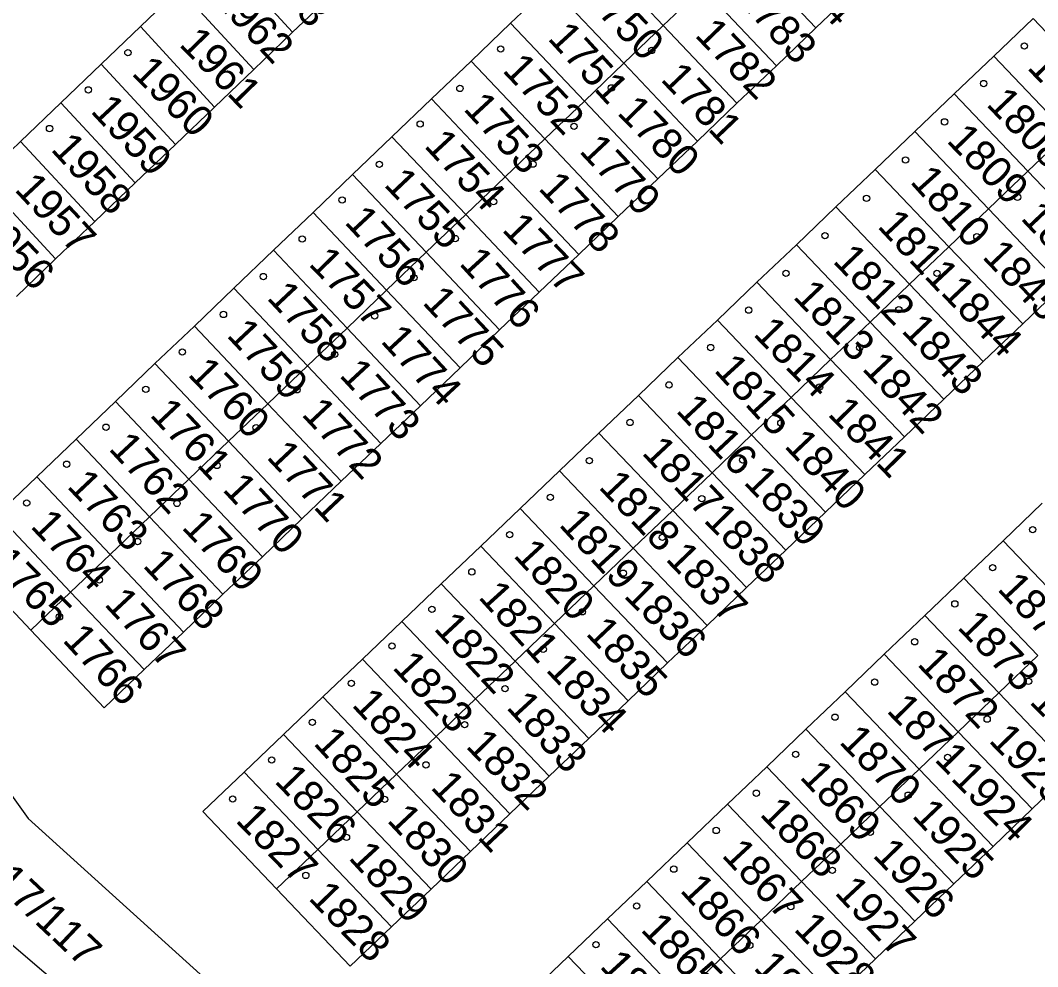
# Model space of a CAD drawing. Extents: x -735249 to -729401, y -1124843 to -1121828.
# Drawn here: x -733413.7 to -733357.4, y -1123266.5 to -1123214.1 of the extents above; entities that cross this region are included whole.
import ezdxf

# ---------------------------------------------------------------- set-up
doc = ezdxf.new("R2010")
doc.units = 0
for name, color, linetype in [('Vrstva 1', 7, 'Continuous'), ('Vrstva 18', 7, 'Continuous'), ('Vrstva 19', 7, 'Continuous'), ('Vrstva 25', 7, 'Continuous')]:
    doc.layers.add(name, color=color, linetype=linetype)

msp = doc.modelspace()

# ---------------------------------------------------------------- linework, layer by layer
at = {"layer": 'Vrstva 1'}
for points in [[(-733382.16, -1123210.08), (-733378.09, -1123214.39)], [(-733402.71, -1123210.3), (-733398.61, -1123214.76)], [(-733373.72, -1123210.21), (-733369.64, -1123214.52)], [(-733407.04, -1123214.45), (-733404.87, -1123212.36)], [(-733404.87, -1123212.36), (-733400.76, -1123216.82)], [(-733384.35, -1123212.17), (-733386.54, -1123214.26)], [(-733384.35, -1123212.17), (-733380.27, -1123216.47)], [(-733378.09, -1123214.39), (-733375.9, -1123212.3)], [(-733375.9, -1123212.3), (-733371.83, -1123216.61)], [(-733398.61, -1123214.76), (-733396.44, -1123212.69)], [(-733369.64, -1123214.52), (-733367.46, -1123212.43)], [(-733359.8, -1123216.09), (-733357.62, -1123214)], [(-733357.62, -1123214), (-733353.54, -1123218.28)], [(-733409.21, -1123216.52), (-733407.04, -1123214.45)], [(-733407.04, -1123214.45), (-733402.94, -1123218.9)], [(-733386.54, -1123214.26), (-733388.73, -1123216.36)], [(-733386.54, -1123214.26), (-733382.46, -1123218.57)], [(-733380.27, -1123216.47), (-733378.09, -1123214.39)], [(-733378.09, -1123214.39), (-733374.01, -1123218.69)], [(-733371.83, -1123216.61), (-733369.64, -1123214.52)], [(-733400.76, -1123216.82), (-733398.61, -1123214.76)], [(-733361.99, -1123218.17), (-733359.8, -1123216.09)], [(-733359.8, -1123216.09), (-733355.72, -1123220.37)], [(-733411.44, -1123218.66), (-733409.21, -1123216.52)], [(-733409.21, -1123216.52), (-733405.1, -1123220.97)], [(-733402.94, -1123218.9), (-733400.76, -1123216.82)], [(-733388.73, -1123216.36), (-733390.92, -1123218.45)], [(-733388.73, -1123216.36), (-733384.65, -1123220.66)], [(-733382.46, -1123218.57), (-733380.27, -1123216.47)], [(-733380.27, -1123216.47), (-733376.2, -1123220.78)], [(-733374.01, -1123218.69), (-733371.83, -1123216.61)], [(-733390.92, -1123218.45), (-733393.11, -1123220.55)], [(-733390.92, -1123218.45), (-733386.84, -1123222.76)], [(-733384.65, -1123220.66), (-733382.46, -1123218.57)], [(-733382.46, -1123218.57), (-733378.39, -1123222.87)], [(-733364.17, -1123220.26), (-733361.99, -1123218.17)], [(-733361.99, -1123218.17), (-733357.91, -1123222.45)], [(-733413.67, -1123220.8), (-733411.44, -1123218.66)], [(-733411.44, -1123218.66), (-733407.33, -1123223.1)], [(-733405.1, -1123220.97), (-733402.94, -1123218.9)], [(-733376.2, -1123220.78), (-733374.01, -1123218.69)], [(-733366.36, -1123222.35), (-733364.17, -1123220.26)], [(-733364.17, -1123220.26), (-733360.09, -1123224.54)], [(-733415.84, -1123222.87), (-733413.67, -1123220.8)], [(-733413.67, -1123220.8), (-733409.57, -1123225.24)], [(-733393.11, -1123220.55), (-733395.29, -1123222.64)], [(-733393.11, -1123220.55), (-733389.03, -1123224.85)], [(-733386.84, -1123222.76), (-733384.65, -1123220.66)], [(-733384.65, -1123220.66), (-733380.58, -1123224.96)], [(-733378.39, -1123222.87), (-733376.2, -1123220.78)], [(-733357.91, -1123222.45), (-733355.72, -1123220.37)], [(-733407.33, -1123223.1), (-733405.1, -1123220.97)], [(-733368.54, -1123224.43), (-733366.36, -1123222.35)], [(-733366.36, -1123222.35), (-733362.28, -1123226.63)], [(-733360.09, -1123224.54), (-733357.91, -1123222.45)], [(-733357.91, -1123222.45), (-733353.82, -1123226.73)], [(-733415.84, -1123222.87), (-733411.73, -1123227.31)], [(-733409.57, -1123225.24), (-733407.33, -1123223.1)], [(-733395.29, -1123222.64), (-733397.48, -1123224.73)], [(-733395.29, -1123222.64), (-733391.22, -1123226.94)], [(-733389.03, -1123224.85), (-733386.84, -1123222.76)], [(-733386.84, -1123222.76), (-733382.77, -1123227.06)], [(-733380.58, -1123224.96), (-733378.39, -1123222.87)], [(-733397.48, -1123224.73), (-733399.67, -1123226.83)], [(-733397.48, -1123224.73), (-733393.41, -1123229.04)], [(-733370.72, -1123226.52), (-733368.54, -1123224.43)], [(-733368.54, -1123224.43), (-733364.46, -1123228.71)], [(-733362.28, -1123226.63), (-733360.09, -1123224.54)], [(-733360.09, -1123224.54), (-733356.01, -1123228.81)], [(-733436.9, -1123225.24), (-733413.25, -1123258.27)], [(-733411.73, -1123227.31), (-733409.57, -1123225.24)], [(-733391.22, -1123226.94), (-733389.03, -1123224.85)], [(-733389.03, -1123224.85), (-733384.96, -1123229.15)], [(-733382.77, -1123227.06), (-733380.58, -1123224.96)], [(-733399.67, -1123226.83), (-733401.86, -1123228.92)], [(-733399.67, -1123226.83), (-733395.6, -1123231.13)], [(-733393.41, -1123229.04), (-733391.22, -1123226.94)], [(-733391.22, -1123226.94), (-733387.15, -1123231.24)], [(-733372.91, -1123228.6), (-733370.72, -1123226.52)], [(-733370.72, -1123226.52), (-733366.64, -1123230.8)], [(-733364.46, -1123228.71), (-733362.28, -1123226.63)], [(-733362.28, -1123226.63), (-733358.19, -1123230.9)], [(-733413.9, -1123229.38), (-733411.73, -1123227.31)], [(-733384.96, -1123229.15), (-733382.77, -1123227.06)], [(-733375.09, -1123230.69), (-733372.91, -1123228.6)], [(-733372.91, -1123228.6), (-733368.83, -1123232.88)], [(-733366.64, -1123230.8), (-733364.46, -1123228.71)], [(-733364.46, -1123228.71), (-733360.38, -1123232.99)], [(-733401.86, -1123228.92), (-733404.05, -1123231.02)], [(-733401.86, -1123228.92), (-733397.79, -1123233.22)], [(-733395.6, -1123231.13), (-733393.41, -1123229.04)], [(-733393.41, -1123229.04), (-733389.34, -1123233.33)], [(-733387.15, -1123231.24), (-733384.96, -1123229.15)], [(-733358.19, -1123230.9), (-733356.01, -1123228.81)], [(-733377.28, -1123232.77), (-733375.09, -1123230.69)], [(-733375.09, -1123230.69), (-733371.01, -1123234.97)], [(-733368.83, -1123232.88), (-733366.64, -1123230.8)], [(-733366.64, -1123230.8), (-733362.56, -1123235.07)], [(-733360.38, -1123232.99), (-733358.19, -1123230.9)], [(-733404.05, -1123231.02), (-733406.24, -1123233.1)], [(-733404.05, -1123231.02), (-733399.98, -1123235.32)], [(-733397.79, -1123233.22), (-733395.6, -1123231.13)], [(-733395.6, -1123231.13), (-733391.53, -1123235.43)], [(-733387.15, -1123231.24), (-733389.34, -1123233.33)], [(-733408.42, -1123235.19), (-733406.24, -1123233.1)], [(-733406.24, -1123233.1), (-733402.16, -1123237.4)], [(-733399.98, -1123235.32), (-733397.79, -1123233.22)], [(-733397.79, -1123233.22), (-733393.72, -1123237.52)], [(-733379.46, -1123234.86), (-733377.28, -1123232.77)], [(-733377.28, -1123232.77), (-733373.2, -1123237.05)], [(-733371.01, -1123234.97), (-733368.83, -1123232.88)], [(-733368.83, -1123232.88), (-733364.74, -1123237.16)], [(-733362.56, -1123235.07), (-733360.38, -1123232.99)], [(-733389.34, -1123233.33), (-733391.53, -1123235.43)], [(-733381.65, -1123236.95), (-733379.46, -1123234.86)], [(-733379.46, -1123234.86), (-733375.38, -1123239.14)], [(-733410.6, -1123237.28), (-733408.42, -1123235.19)], [(-733408.42, -1123235.19), (-733404.35, -1123239.49)], [(-733402.16, -1123237.4), (-733399.98, -1123235.32)], [(-733399.98, -1123235.32), (-733395.92, -1123239.61)], [(-733391.53, -1123235.43), (-733393.72, -1123237.52)], [(-733373.2, -1123237.05), (-733371.01, -1123234.97)], [(-733371.01, -1123234.97), (-733366.93, -1123239.24)], [(-733364.74, -1123237.16), (-733362.56, -1123235.07)], [(-733383.83, -1123239.03), (-733381.65, -1123236.95)], [(-733381.65, -1123236.95), (-733377.57, -1123241.23)], [(-733375.38, -1123239.14), (-733373.2, -1123237.05)], [(-733373.2, -1123237.05), (-733369.11, -1123241.33)], [(-733366.93, -1123239.24), (-733364.74, -1123237.16)], [(-733410.6, -1123237.28), (-733412.78, -1123239.37)], [(-733410.6, -1123237.28), (-733406.53, -1123241.58)], [(-733404.35, -1123239.49), (-733402.16, -1123237.4)], [(-733402.16, -1123237.4), (-733398.1, -1123241.7)], [(-733393.72, -1123237.52), (-733395.92, -1123239.61)], [(-733412.78, -1123239.37), (-733414.97, -1123241.45)], [(-733412.78, -1123239.37), (-733408.71, -1123243.67)], [(-733386.01, -1123241.12), (-733383.83, -1123239.03)], [(-733383.83, -1123239.03), (-733379.75, -1123243.31)], [(-733377.57, -1123241.23), (-733375.38, -1123239.14)], [(-733375.38, -1123239.14), (-733371.3, -1123243.42)], [(-733369.11, -1123241.33), (-733366.93, -1123239.24)], [(-733406.53, -1123241.58), (-733404.35, -1123239.49)], [(-733404.35, -1123239.49), (-733400.28, -1123243.79)], [(-733395.92, -1123239.61), (-733398.1, -1123241.7)], [(-733388.2, -1123243.2), (-733386.01, -1123241.12)], [(-733386.01, -1123241.12), (-733381.93, -1123245.4)], [(-733359.28, -1123242.91), (-733357.11, -1123240.83)], [(-733414.97, -1123241.45), (-733410.9, -1123245.75)], [(-733408.71, -1123243.67), (-733406.53, -1123241.58)], [(-733406.53, -1123241.58), (-733402.47, -1123245.87)], [(-733379.75, -1123243.31), (-733377.57, -1123241.23)], [(-733377.57, -1123241.23), (-733373.48, -1123245.5)], [(-733371.3, -1123243.42), (-733369.11, -1123241.33)], [(-733398.1, -1123241.7), (-733400.28, -1123243.79)], [(-733390.38, -1123245.29), (-733388.2, -1123243.2)], [(-733388.2, -1123243.2), (-733384.12, -1123247.48)], [(-733381.93, -1123245.4), (-733379.75, -1123243.31)], [(-733379.75, -1123243.31), (-733375.66, -1123247.59)], [(-733361.45, -1123244.98), (-733359.28, -1123242.91)], [(-733359.28, -1123242.91), (-733355.18, -1123247.19)], [(-733417.17, -1123243.56), (-733413.1, -1123247.86)], [(-733410.9, -1123245.75), (-733408.71, -1123243.67)], [(-733408.71, -1123243.67), (-733404.65, -1123247.96)], [(-733400.28, -1123243.79), (-733402.47, -1123245.87)], [(-733373.48, -1123245.5), (-733371.3, -1123243.42)], [(-733363.61, -1123247.05), (-733361.45, -1123244.98)], [(-733361.45, -1123244.98), (-733357.35, -1123249.26)], [(-733392.57, -1123247.37), (-733390.38, -1123245.29)], [(-733390.38, -1123245.29), (-733386.3, -1123249.57)], [(-733384.12, -1123247.48), (-733381.93, -1123245.4)], [(-733381.93, -1123245.4), (-733377.85, -1123249.67)], [(-733375.66, -1123247.59), (-733373.48, -1123245.5)], [(-733413.1, -1123247.86), (-733410.9, -1123245.75)], [(-733410.9, -1123245.75), (-733406.83, -1123250.04)], [(-733402.47, -1123245.87), (-733404.65, -1123247.96)], [(-733365.86, -1123249.19), (-733363.61, -1123247.05)], [(-733363.61, -1123247.05), (-733359.52, -1123251.33)], [(-733413.1, -1123247.86), (-733409.04, -1123252.15)], [(-733394.75, -1123249.46), (-733392.57, -1123247.37)], [(-733392.57, -1123247.37), (-733388.49, -1123251.65)], [(-733386.3, -1123249.57), (-733384.12, -1123247.48)], [(-733384.12, -1123247.48), (-733380.03, -1123251.76)], [(-733377.85, -1123249.67), (-733375.66, -1123247.59)], [(-733404.65, -1123247.96), (-733406.83, -1123250.04)], [(-733396.94, -1123251.55), (-733394.75, -1123249.46)], [(-733394.75, -1123249.46), (-733390.67, -1123253.74)], [(-733388.49, -1123251.65), (-733386.3, -1123249.57)], [(-733386.3, -1123249.57), (-733382.22, -1123253.85)], [(-733368.02, -1123251.27), (-733365.86, -1123249.19)], [(-733365.86, -1123249.19), (-733361.76, -1123253.48)], [(-733359.52, -1123251.33), (-733357.35, -1123249.26)], [(-733406.83, -1123250.04), (-733409.04, -1123252.15)], [(-733380.03, -1123251.76), (-733377.85, -1123249.67)], [(-733370.19, -1123253.34), (-733368.02, -1123251.27)], [(-733368.02, -1123251.27), (-733363.93, -1123255.55)], [(-733399.12, -1123253.63), (-733396.94, -1123251.55)], [(-733396.94, -1123251.55), (-733392.86, -1123255.83)], [(-733390.67, -1123253.74), (-733388.49, -1123251.65)], [(-733388.49, -1123251.65), (-733384.4, -1123255.93)], [(-733382.22, -1123253.85), (-733380.03, -1123251.76)], [(-733361.76, -1123253.48), (-733359.52, -1123251.33)], [(-733359.52, -1123251.33), (-733355.43, -1123255.61)], [(-733372.36, -1123255.41), (-733370.19, -1123253.34)], [(-733370.19, -1123253.34), (-733366.1, -1123257.62)], [(-733363.93, -1123255.55), (-733361.76, -1123253.48)], [(-733361.76, -1123253.48), (-733357.67, -1123257.75)], [(-733401.3, -1123255.72), (-733399.12, -1123253.63)], [(-733399.12, -1123253.63), (-733395.04, -1123257.91)], [(-733392.86, -1123255.83), (-733390.67, -1123253.74)], [(-733390.67, -1123253.74), (-733386.58, -1123258.02)], [(-733384.4, -1123255.93), (-733382.22, -1123253.85)], [(-733403.59, -1123257.9), (-733401.3, -1123255.72)], [(-733401.3, -1123255.72), (-733397.22, -1123260)], [(-733374.53, -1123257.48), (-733372.36, -1123255.41)], [(-733372.36, -1123255.41), (-733368.27, -1123259.7)], [(-733366.1, -1123257.62), (-733363.93, -1123255.55)], [(-733363.93, -1123255.55), (-733359.83, -1123259.83)], [(-733357.67, -1123257.75), (-733355.43, -1123255.61)], [(-733395.04, -1123257.91), (-733392.86, -1123255.83)], [(-733392.86, -1123255.83), (-733388.77, -1123260.11)], [(-733386.58, -1123258.02), (-733384.4, -1123255.93)], [(-733403.59, -1123257.9), (-733399.51, -1123262.18)], [(-733397.22, -1123260), (-733395.04, -1123257.91)], [(-733395.04, -1123257.91), (-733390.95, -1123262.19)], [(-733388.77, -1123260.11), (-733386.58, -1123258.02)], [(-733376.77, -1123259.63), (-733374.53, -1123257.48)], [(-733374.53, -1123257.48), (-733370.44, -1123261.77)], [(-733368.27, -1123259.7), (-733366.1, -1123257.62)], [(-733366.1, -1123257.62), (-733362, -1123261.9)], [(-733359.83, -1123259.83), (-733357.67, -1123257.75)], [(-733413.25, -1123258.27), (-733359.58, -1123306.83)], [(-733421.63, -1123258.87), (-733396.24, -1123280.58)], [(-733379.01, -1123261.77), (-733376.77, -1123259.63)], [(-733376.77, -1123259.63), (-733372.68, -1123263.91)], [(-733370.44, -1123261.77), (-733368.27, -1123259.7)], [(-733368.27, -1123259.7), (-733364.17, -1123263.97)], [(-733399.51, -1123262.18), (-733397.22, -1123260)], [(-733397.22, -1123260), (-733393.13, -1123264.28)], [(-733390.95, -1123262.19), (-733388.77, -1123260.11)], [(-733362, -1123261.9), (-733359.83, -1123259.83)], [(-733381.18, -1123263.84), (-733379.01, -1123261.77)], [(-733379.01, -1123261.77), (-733374.92, -1123266.05)], [(-733372.68, -1123263.91), (-733370.44, -1123261.77)], [(-733370.44, -1123261.77), (-733366.34, -1123266.05)], [(-733364.17, -1123263.97), (-733362, -1123261.9)], [(-733399.51, -1123262.18), (-733395.42, -1123266.46)], [(-733393.13, -1123264.28), (-733390.95, -1123262.19)], [(-733383.35, -1123265.91), (-733381.18, -1123263.84)], [(-733381.18, -1123263.84), (-733377.08, -1123268.13)], [(-733374.92, -1123266.05), (-733372.68, -1123263.91)], [(-733372.68, -1123263.91), (-733368.58, -1123268.19)], [(-733366.34, -1123266.05), (-733364.17, -1123263.97)], [(-733395.42, -1123266.46), (-733393.13, -1123264.28)], [(-733385.52, -1123267.99), (-733383.35, -1123265.91)], [(-733383.35, -1123265.91), (-733379.25, -1123270.2)], [(-733377.08, -1123268.13), (-733374.92, -1123266.05)], [(-733374.92, -1123266.05), (-733370.82, -1123270.33)], [(-733368.58, -1123268.19), (-733366.34, -1123266.05)]]:
    msp.add_lwpolyline(points, dxfattribs=at)
at = {"layer": 'Vrstva 25'}
for centre in [(-733407.73, -1123215.89), (-733387.09, -1123215.69), (-733378.73, -1123215.77), (-733358.1, -1123215.52), (-733360.35, -1123217.6), (-733409.92, -1123217.95), (-733389.35, -1123217.87), (-733380.96, -1123217.84), (-733391.55, -1123219.84), (-733362.52, -1123219.72), (-733412.07, -1123220.09), (-733383.03, -1123219.97), (-733393.81, -1123222.07), (-733385.31, -1123222.06), (-733364.68, -1123221.83), (-733395.87, -1123224.05), (-733387.49, -1123224.14), (-733366.84, -1123223.95), (-733358.48, -1123223.89), (-733369.14, -1123226.02), (-733360.73, -1123226.07), (-733398.08, -1123226.2), (-733389.61, -1123226.18), (-733400.23, -1123228.28), (-733391.9, -1123228.34), (-733371.3, -1123228.1), (-733362.94, -1123228.1), (-733402.44, -1123230.38), (-733394.07, -1123230.46), (-733373.36, -1123230.14), (-733365.05, -1123230.12), (-733375.47, -1123232.21), (-733367.22, -1123232.22), (-733404.72, -1123232.46), (-733396.28, -1123232.59), (-733406.74, -1123234.52), (-733377.77, -1123234.28), (-733369.44, -1123234.4), (-733398.37, -1123234.55), (-733408.94, -1123236.62), (-733400.63, -1123236.65), (-733379.93, -1123236.36), (-733371.58, -1123236.39), (-733382.18, -1123238.47), (-733373.7, -1123238.44), (-733411.12, -1123238.67), (-733402.8, -1123238.74), (-733384.34, -1123240.5), (-733375.96, -1123240.58), (-733413.33, -1123240.82), (-733405.01, -1123240.84), (-733357.64, -1123242.29), (-733407.19, -1123242.95), (-733386.6, -1123242.57), (-733378.14, -1123242.72), (-733388.69, -1123244.63), (-733359.86, -1123244.4), (-733409.31, -1123245.07), (-733380.31, -1123244.7), (-733390.9, -1123246.7), (-733382.57, -1123246.84), (-733361.95, -1123246.4), (-733411.52, -1123247.12), (-733364.17, -1123248.5), (-733393.11, -1123248.73), (-733384.74, -1123248.91), (-733395.36, -1123250.8), (-733366.39, -1123250.73), (-733357.87, -1123250.69), (-733386.85, -1123251.09), (-733397.52, -1123252.96), (-733389.09, -1123253.09), (-733368.58, -1123252.67), (-733360.16, -1123252.78), (-733370.76, -1123254.73), (-733399.77, -1123255.04), (-733391.23, -1123255.31), (-733362.35, -1123254.89), (-733372.94, -1123256.88), (-733364.53, -1123256.99), (-733401.93, -1123257.2), (-733393.52, -1123257.22), (-733395.63, -1123259.32), (-733375.16, -1123258.94), (-733366.63, -1123259.04), (-733397.88, -1123261.43), (-733377.51, -1123261.08), (-733368.73, -1123261.15), (-733379.56, -1123263.12), (-733371.03, -1123263.16), (-733381.82, -1123265.26), (-733373.3, -1123265.3)]:
    msp.add_circle(centre, 0.175, dxfattribs=at)

# ---------------------------------------------------------------- texts
at = {"layer": 'Vrstva 18'}
msp.add_text('217/117', height=1.7, rotation=316.6025, dxfattribs=at).set_placement((-733416.168, -1123260.983))
at = {"layer": 'Vrstva 19'}
for s, rotation, p in [('1963', 312.9025, (-733401.058, -1123210.91)), ('1784', 313.1025, (-733371.998, -1123210.859)), ('1962', 313.0025, (-733403.098, -1123212.919)), ('1750', 314.1025, (-733382.648, -1123212.814)), ('1783', 312.4025, (-733374.118, -1123212.902)), ('1961', 314.3025, (-733404.948, -1123215.473)), ('1751', 312.5025, (-733384.538, -1123215.132)), ('1782', 314.0025, (-733376.398, -1123214.964)), ('1960', 314.4025, (-733407.578, -1123217.072)), ('1752', 313.7025, (-733387.048, -1123216.906)), ('1807', 313.9025, (-733357.998, -1123216.755)), ('1781', 313.6025, (-733378.288, -1123217.406)), ('1808', 313.7025, (-733360.258, -1123218.786)), ('1959', 313.0025, (-733409.848, -1123219.159)), ('1753', 312.8025, (-733389.208, -1123219.03)), ('1780', 314.6025, (-733380.698, -1123219.261)), ('1754', 312.8025, (-733391.378, -1123221.08)), ('1809', 314.1025, (-733362.458, -1123220.804)), ('1958', 312.6025, (-733412.048, -1123221.271)), ('1779', 313.2025, (-733382.798, -1123221.368)), ('1755', 313.4025, (-733393.608, -1123223.227)), ('1810', 311.9025, (-733364.478, -1123223.055)), ('1957', 313.1025, (-733414.058, -1123223.499)), ('1778', 313.3025, (-733385.058, -1123223.438)), ('1956', 313.4025, (-733416.358, -1123225.477)), ('1756', 313.0025, (-733395.788, -1123225.309)), ('1811', 313.1025, (-733366.288, -1123225.529)), ('1846', 313.4025, (-733358.358, -1123225.087)), ('1777', 313.9025, (-733387.078, -1123225.725)), ('1845', 313.8025, (-733360.488, -1123227.225)), ('1757', 314.2025, (-733397.778, -1123227.623)), ('1776', 312.4025, (-733389.438, -1123227.592)), ('1812', 313.9025, (-733368.758, -1123227.465)), ('1758', 313.2025, (-733400.088, -1123229.498)), ('1813', 313.6025, (-733370.958, -1123229.436)), ('1844', 313.5025, (-733362.788, -1123229.207)), ('1775', 313.2025, (-733391.478, -1123229.758)), ('1759', 313.2025, (-733402.318, -1123231.568)), ('1814', 314.3025, (-733373.168, -1123231.503)), ('1843', 313.5025, (-733364.958, -1123231.317)), ('1774', 312.8025, (-733393.788, -1123231.89)), ('1842', 313.2025, (-733367.138, -1123233.418)), ('1760', 314.0025, (-733404.468, -1123233.734)), ('1773', 312.9025, (-733396.078, -1123233.78)), ('1815', 312.4025, (-733375.328, -1123233.502)), ('1816', 313.1025, (-733377.438, -1123235.739)), ('1761', 313.3025, (-733406.568, -1123235.978)), ('1772', 313.2025, (-733398.168, -1123235.938)), ('1841', 314.5025, (-733369.038, -1123235.932)), ('1762', 312.9025, (-733408.848, -1123237.84)), ('1840', 313.5025, (-733371.448, -1123237.697)), ('1771', 313.3025, (-733400.108, -1123238.308)), ('1817', 313.2025, (-733379.328, -1123238.078)), ('1763', 313.4025, (-733411.158, -1123239.927)), ('1770', 313.0025, (-733402.548, -1123240.099)), ('1818', 313.4025, (-733381.718, -1123239.967)), ('1839', 313.6025, (-733373.698, -1123239.706)), ('1838', 314.4025, (-733375.908, -1123241.812)), ('1764', 313.5025, (-733413.178, -1123242.137)), ('1769', 313.5025, (-733404.808, -1123242.197)), ('1819', 312.6025, (-733383.918, -1123242.051)), ('1820', 312.7025, (-733386.438, -1123243.751)), ('1837', 313.8025, (-733378.018, -1123243.955)), ('1765', 314.4025, (-733415.438, -1123244.232)), ('1768', 313.5025, (-733406.958, -1123244.317)), ('1874', 313.2025, (-733359.648, -1123245.608)), ('1767', 313.0025, (-733409.088, -1123246.449)), ('1821', 312.2025, (-733388.378, -1123246.053)), ('1836', 315.5025, (-733380.338, -1123245.998)), ('1822', 312.9025, (-733390.848, -1123247.8)), ('1835', 313.6025, (-733382.438, -1123248.076)), ('1873', 314.1025, (-733361.868, -1123247.734)), ('1766', 312.7025, (-733411.398, -1123248.441)), ('1872', 313.8025, (-733364.088, -1123249.765)), ('1823', 312.8025, (-733393.138, -1123249.95)), ('1834', 313.5025, (-733384.648, -1123250.087)), ('1824', 313.4025, (-733395.388, -1123252.027)), ('1922', 314.4025, (-733357.868, -1123251.862)), ('1833', 312.6025, (-733386.828, -1123252.161)), ('1871', 314.5025, (-733365.788, -1123252.352)), ('1825', 312.8025, (-733397.508, -1123254.15)), ('1832', 314.4025, (-733389.078, -1123254.322)), ('1870', 314.2025, (-733368.408, -1123254.083)), ('1923', 314.1025, (-733360.128, -1123254.004)), ('1869', 313.1025, (-733370.588, -1123256.019)), ('1826', 314.2025, (-733399.668, -1123256.253)), ('1831', 313.3025, (-733391.028, -1123256.588)), ('1924', 314.4025, (-733362.228, -1123256.102)), ('1868', 314.4025, (-733372.808, -1123258.082)), ('1925', 313.7025, (-733364.378, -1123258.166)), ('1827', 314.3025, (-733401.828, -1123258.423)), ('1830', 313.2025, (-733393.438, -1123258.418)), ('1829', 312.6025, (-733395.568, -1123260.481)), ('1867', 312.9025, (-733374.908, -1123260.35)), ('1926', 314.2025, (-733366.558, -1123260.353)), ('1828', 314.3025, (-733397.788, -1123262.733)), ('1866', 312.8025, (-733377.218, -1123262.29)), ('1927', 313.0025, (-733368.658, -1123262.419)), ('1865', 314.1025, (-733379.398, -1123264.474)), ('1928', 313.7025, (-733370.918, -1123264.436)), ('1864', 312.5025, (-733381.658, -1123266.492)), ('1929', 313.5025, (-733373.148, -1123266.577))]:
    msp.add_text(s, height=1.7, rotation=rotation, dxfattribs=at).set_placement(p)

doc.saveas('drawing.dxf')
